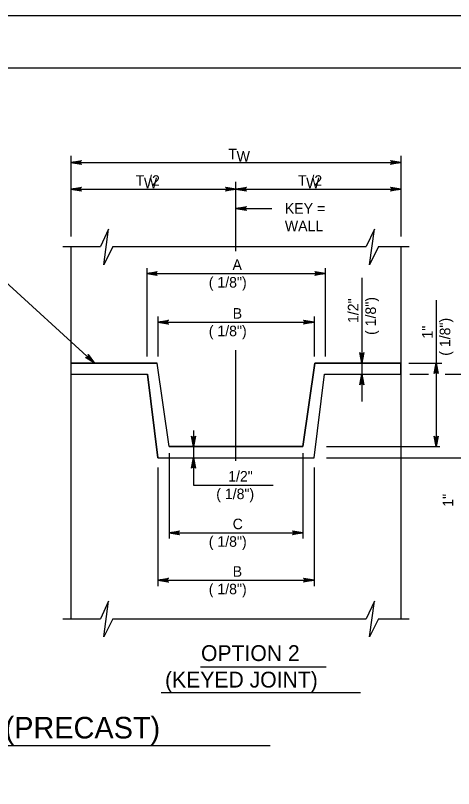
# Model space of a CAD drawing. Extents: x 2106427 to 2114911, y 988717 to 990787.
# Drawn here: x 2113594 to 2114003, y 990066 to 990787 of the extents above; entities that cross this region are included whole.
import ezdxf

# ---------------------------------------------------------------- set-up
doc = ezdxf.new("R2010")
doc.units = 0
for name, color, linetype in [('1', 7, 'Continuous'), ('3', 7, 'Continuous'), ('PLT-BNDY', 7, 'Continuous')]:
    doc.layers.add(name, color=color, linetype=linetype)

msp = doc.modelspace()

# ---------------------------------------------------------------- linework, layer by layer
at = {"layer": '1'}
for p, q in [((2113668.04, 990462.73), (2113413.04, 990695.31)), ((2113645.92, 990656.31), (2113645.92, 990580.81)), ((2113954.08, 990656.31), (2113954.08, 990580.81)), ((2113645.92, 990650.07), (2113954.08, 990650.07)), ((2113800, 990567.15), (2113800, 990631.9)), ((2113645.92, 990625.07), (2113800, 990625.07)), ((2113800, 990625.07), (2113954.08, 990625.07)), ((2113800, 990607.15), (2113833.59, 990607.15)), ((2113638.39, 990571.62), (2113673.37, 990571.62)), ((2113645.92, 990571.62), (2113645.92, 990224.14)), ((2113684.91, 990571.62), (2113921.57, 990571.62)), ((2113933.12, 990571.62), (2113961.82, 990571.62)), ((2113954.08, 990571.62), (2113954.08, 990224.14)), ((2113716.7, 990551.45), (2113716.7, 990469)), ((2113883.3, 990551.45), (2113883.3, 990469)), ((2113716.7, 990546.39), (2113883.3, 990546.39)), ((2113917.6, 990542.37), (2113917.6, 990426.83)), ((2113986.98, 990521.47), (2113986.98, 990384.77)), ((2113727.1, 990506.28), (2113727.1, 990469)), ((2113872.9, 990506.28), (2113872.9, 990469)), ((2113727.1, 990500.97), (2113872.9, 990500.97)), ((2113800, 990371.42), (2113800, 990474.89)), ((2113645.92, 990462.73), (2113726.38, 990462.73)), ((2113737.5, 990384.77), (2113726.38, 990462.73)), ((2113862.5, 990384.77), (2113873.62, 990462.73)), ((2113873.62, 990462.73), (2113954.08, 990462.73)), ((2113961.41, 990462.73), (2113992.31, 990462.73)), ((2113645.92, 990452.33), (2113717.37, 990452.33)), ((2113727.1, 990374.37), (2113717.37, 990452.33)), ((2113872.9, 990374.37), (2113882.63, 990452.33)), ((2113882.63, 990452.33), (2113954.08, 990452.33)), ((2113962.49, 990452.33), (2113979.72, 990452.33)), ((2113995.36, 990452.33), (2114012.79, 990452.33)), ((2113760.38, 990399.89), (2113760.38, 990348.86)), ((2113737.5, 990384.77), (2113862.5, 990384.77)), ((2113884.51, 990384.77), (2113990.36, 990384.77)), ((2113737.5, 990378.55), (2113737.5, 990298.84)), ((2113862.5, 990378.55), (2113862.5, 990298.84)), ((2113727.1, 990374.37), (2113872.9, 990374.37)), ((2113884.51, 990374.37), (2114011.3, 990374.37)), ((2113727.1, 990365.41), (2113727.1, 990254.47)), ((2113872.9, 990365.41), (2113872.9, 990254.47)), ((2113760.38, 990348.86), (2113834.77, 990348.86)), ((2113737.5, 990304.37), (2113862.5, 990304.37)), ((2113727.1, 990260.02), (2113872.9, 990260.02)), ((2113638.39, 990224.14), (2113673.37, 990224.14)), ((2113684.91, 990224.14), (2113921.57, 990224.14)), ((2113933.12, 990224.14), (2113961.82, 990224.14)), ((2113766.99, 990179.08), (2113884.25, 990179.08)), ((2113730.28, 990155.32), (2113916.43, 990155.32)), ((2113375.97, 990105.8), (2113831.83, 990105.8))]:
    msp.add_line(p, q, dxfattribs=at)
for points in [[(2114651.58, 988887.71), (2114651.58, 990738.11), (2112072.84, 990738.11), (2112072.84, 988887.71), (2114651.58, 988887.71), (2114651.58, 988974.19), (2113995.41, 988974.19), (2113995.41, 989186.39), (2114651.58, 989186.39), (2114651.58, 989281.41), (2113995.41, 989281.41), (2113995.41, 988887.71), (2114253.94, 988887.71), (2114253.94, 988974.19), (2114253.94, 988887.71), (2114506.57, 988887.71), (2114506.57, 988974.19), (2114506.57, 988933.79), (2114651.58, 988933.79)], [(2113645.92, 990650.07), (2113655.71, 990651.91), (2113655.33, 990651.65), (2113654.95, 990651.39), (2113654.76, 990651.06), (2113654.57, 990650.73), (2113654.51, 990650.4), (2113654.45, 990650.07), (2113654.51, 990649.75), (2113654.57, 990649.42), (2113654.76, 990649.09), (2113654.95, 990648.76), (2113655.33, 990648.5), (2113655.71, 990648.24), (2113645.92, 990650.07), (2113655.33, 990648.5), (2113654.95, 990648.76), (2113645.92, 990650.07), (2113654.76, 990649.09), (2113654.57, 990649.42), (2113645.92, 990650.07), (2113654.51, 990649.75), (2113654.45, 990650.07), (2113645.92, 990650.07), (2113654.51, 990650.4), (2113654.57, 990650.73), (2113645.92, 990650.07), (2113654.76, 990651.06), (2113654.95, 990651.39), (2113645.92, 990650.07), (2113655.33, 990651.65)], [(2113954.08, 990650.07), (2113944.29, 990648.24), (2113944.67, 990648.5), (2113945.05, 990648.76), (2113945.24, 990649.09), (2113945.44, 990649.42), (2113945.49, 990649.75), (2113945.55, 990650.07), (2113945.49, 990650.4), (2113945.44, 990650.73), (2113945.24, 990651.06), (2113945.05, 990651.39), (2113944.67, 990651.65), (2113944.29, 990651.91), (2113954.08, 990650.07), (2113944.67, 990651.65), (2113945.05, 990651.39), (2113954.08, 990650.07), (2113945.24, 990651.06), (2113945.44, 990650.73), (2113954.08, 990650.07), (2113945.49, 990650.4), (2113945.55, 990650.07), (2113954.08, 990650.07), (2113945.49, 990649.75), (2113945.44, 990649.42), (2113954.08, 990650.07), (2113945.24, 990649.09), (2113945.05, 990648.76), (2113954.08, 990650.07), (2113944.67, 990648.5)], [(2113645.92, 990625.07), (2113655.71, 990626.91), (2113655.33, 990626.65), (2113654.95, 990626.39), (2113654.76, 990626.06), (2113654.57, 990625.73), (2113654.51, 990625.4), (2113654.45, 990625.07), (2113654.51, 990624.75), (2113654.57, 990624.42), (2113654.76, 990624.09), (2113654.95, 990623.76), (2113655.33, 990623.5), (2113655.71, 990623.24), (2113645.92, 990625.07), (2113655.33, 990623.5), (2113654.95, 990623.76), (2113645.92, 990625.07), (2113654.76, 990624.09), (2113654.57, 990624.42), (2113645.92, 990625.07), (2113654.51, 990624.75), (2113654.45, 990625.07), (2113645.92, 990625.07), (2113654.51, 990625.4), (2113654.57, 990625.73), (2113645.92, 990625.07), (2113654.76, 990626.06), (2113654.95, 990626.39), (2113645.92, 990625.07), (2113655.33, 990626.65)], [(2113800, 990625.07), (2113790.22, 990623.24), (2113790.59, 990623.5), (2113790.97, 990623.76), (2113791.16, 990624.09), (2113791.36, 990624.42), (2113791.41, 990624.75), (2113791.47, 990625.07), (2113791.41, 990625.4), (2113791.36, 990625.73), (2113791.16, 990626.06), (2113790.97, 990626.39), (2113790.59, 990626.65), (2113790.22, 990626.91), (2113800, 990625.07), (2113790.59, 990626.65), (2113790.97, 990626.39), (2113800, 990625.07), (2113791.16, 990626.06), (2113791.36, 990625.73), (2113800, 990625.07), (2113791.41, 990625.4), (2113791.47, 990625.07), (2113800, 990625.07), (2113791.41, 990624.75), (2113791.36, 990624.42), (2113800, 990625.07), (2113791.16, 990624.09), (2113790.97, 990623.76), (2113800, 990625.07), (2113790.59, 990623.5)], [(2113800, 990625.07), (2113809.79, 990626.91), (2113809.41, 990626.65), (2113809.03, 990626.39), (2113808.84, 990626.06), (2113808.64, 990625.73), (2113808.59, 990625.4), (2113808.53, 990625.07), (2113808.59, 990624.75), (2113808.64, 990624.42), (2113808.84, 990624.09), (2113809.03, 990623.76), (2113809.41, 990623.5), (2113809.79, 990623.24), (2113800, 990625.07), (2113809.41, 990623.5), (2113809.03, 990623.76), (2113800, 990625.07), (2113808.84, 990624.09), (2113808.64, 990624.42), (2113800, 990625.07), (2113808.59, 990624.75), (2113808.53, 990625.07), (2113800, 990625.07), (2113808.59, 990625.4), (2113808.64, 990625.73), (2113800, 990625.07), (2113808.84, 990626.06), (2113809.03, 990626.39), (2113800, 990625.07), (2113809.41, 990626.65)], [(2113954.08, 990625.07), (2113944.29, 990623.24), (2113944.67, 990623.5), (2113945.05, 990623.76), (2113945.24, 990624.09), (2113945.44, 990624.42), (2113945.49, 990624.75), (2113945.55, 990625.07), (2113945.49, 990625.4), (2113945.44, 990625.73), (2113945.24, 990626.06), (2113945.05, 990626.39), (2113944.67, 990626.65), (2113944.29, 990626.91), (2113954.08, 990625.07), (2113944.67, 990626.65), (2113945.05, 990626.39), (2113954.08, 990625.07), (2113945.24, 990626.06), (2113945.44, 990625.73), (2113954.08, 990625.07), (2113945.49, 990625.4), (2113945.55, 990625.07), (2113954.08, 990625.07), (2113945.49, 990624.75), (2113945.44, 990624.42), (2113954.08, 990625.07), (2113945.24, 990624.09), (2113945.05, 990623.76), (2113954.08, 990625.07), (2113944.67, 990623.5)], [(2113800, 990607.15), (2113809.79, 990608.98), (2113809.41, 990608.72), (2113809.03, 990608.46), (2113808.84, 990608.13), (2113808.64, 990607.8), (2113808.59, 990607.48), (2113808.53, 990607.15), (2113808.59, 990606.82), (2113808.64, 990606.49), (2113808.84, 990606.16), (2113809.03, 990605.84), (2113809.41, 990605.57), (2113809.79, 990605.31), (2113800, 990607.15), (2113809.41, 990605.57), (2113809.03, 990605.84), (2113800, 990607.15), (2113808.84, 990606.16), (2113808.64, 990606.49), (2113800, 990607.15), (2113808.59, 990606.82), (2113808.53, 990607.15), (2113800, 990607.15), (2113808.59, 990607.48), (2113808.64, 990607.8), (2113800, 990607.15), (2113808.84, 990608.13), (2113809.03, 990608.46), (2113800, 990607.15), (2113809.41, 990608.72)], [(2113684.91, 990571.62), (2113676.59, 990554.6), (2113681.12, 990587.9), (2113673.37, 990571.62)], [(2113933.12, 990571.62), (2113924.79, 990554.6), (2113929.32, 990587.9), (2113921.57, 990571.62)], [(2113716.7, 990546.39), (2113726.49, 990548.23), (2113726.11, 990547.96), (2113725.73, 990547.7), (2113725.54, 990547.38), (2113725.34, 990547.05), (2113725.29, 990546.72), (2113725.23, 990546.39), (2113725.29, 990546.06), (2113725.34, 990545.74), (2113725.54, 990545.41), (2113725.73, 990545.08), (2113726.11, 990544.82), (2113726.49, 990544.56), (2113716.7, 990546.39), (2113726.11, 990544.82), (2113725.73, 990545.08), (2113716.7, 990546.39), (2113725.54, 990545.41), (2113725.34, 990545.74), (2113716.7, 990546.39), (2113725.29, 990546.06), (2113725.23, 990546.39), (2113716.7, 990546.39), (2113725.29, 990546.72), (2113725.34, 990547.05), (2113716.7, 990546.39), (2113725.54, 990547.38), (2113725.73, 990547.7), (2113716.7, 990546.39), (2113726.11, 990547.96)], [(2113883.3, 990546.39), (2113873.52, 990544.56), (2113873.89, 990544.82), (2113874.27, 990545.08), (2113874.46, 990545.41), (2113874.66, 990545.74), (2113874.71, 990546.06), (2113874.77, 990546.39), (2113874.71, 990546.72), (2113874.66, 990547.05), (2113874.46, 990547.38), (2113874.27, 990547.7), (2113873.89, 990547.96), (2113873.52, 990548.23), (2113883.3, 990546.39), (2113873.89, 990547.96), (2113874.27, 990547.7), (2113883.3, 990546.39), (2113874.46, 990547.38), (2113874.66, 990547.05), (2113883.3, 990546.39), (2113874.71, 990546.72), (2113874.77, 990546.39), (2113883.3, 990546.39), (2113874.71, 990546.06), (2113874.66, 990545.74), (2113883.3, 990546.39), (2113874.46, 990545.41), (2113874.27, 990545.08), (2113883.3, 990546.39), (2113873.89, 990544.82)], [(2113727.1, 990500.97), (2113736.89, 990502.81), (2113736.51, 990502.55), (2113736.13, 990502.28), (2113735.94, 990501.96), (2113735.74, 990501.63), (2113735.69, 990501.3), (2113735.63, 990500.97), (2113735.69, 990500.64), (2113735.74, 990500.32), (2113735.94, 990499.99), (2113736.13, 990499.66), (2113736.51, 990499.4), (2113736.89, 990499.14), (2113727.1, 990500.97), (2113736.51, 990499.4), (2113736.13, 990499.66), (2113727.1, 990500.97), (2113735.94, 990499.99), (2113735.74, 990500.32), (2113727.1, 990500.97), (2113735.69, 990500.64), (2113735.63, 990500.97), (2113727.1, 990500.97), (2113735.69, 990501.3), (2113735.74, 990501.63), (2113727.1, 990500.97), (2113735.94, 990501.96), (2113736.13, 990502.28), (2113727.1, 990500.97), (2113736.51, 990502.55)], [(2113872.9, 990500.97), (2113863.12, 990499.14), (2113863.49, 990499.4), (2113863.87, 990499.66), (2113864.06, 990499.99), (2113864.26, 990500.32), (2113864.31, 990500.64), (2113864.37, 990500.97), (2113864.31, 990501.3), (2113864.26, 990501.63), (2113864.06, 990501.96), (2113863.87, 990502.28), (2113863.49, 990502.55), (2113863.12, 990502.81), (2113872.9, 990500.97), (2113863.49, 990502.55), (2113863.87, 990502.28), (2113872.9, 990500.97), (2113864.06, 990501.96), (2113864.26, 990501.63), (2113872.9, 990500.97), (2113864.31, 990501.3), (2113864.37, 990500.97), (2113872.9, 990500.97), (2113864.31, 990500.64), (2113864.26, 990500.32), (2113872.9, 990500.97), (2113864.06, 990499.99), (2113863.87, 990499.66), (2113872.9, 990500.97), (2113863.49, 990499.4)], [(2113668.04, 990462.73), (2113659.57, 990467.97), (2113660.48, 990467.85), (2113661.21, 990468.07), (2113661.74, 990468.48), (2113662.09, 990469.04), (2113662.25, 990469.79), (2113662.04, 990470.68), (2113668.04, 990462.73), (2113662.25, 990469.79), (2113662.09, 990469.04), (2113668.04, 990462.73), (2113661.74, 990468.48), (2113661.21, 990468.07), (2113668.04, 990462.73), (2113660.48, 990467.85)], [(2113917.6, 990462.73), (2113915.76, 990472.52), (2113916.02, 990472.14), (2113916.28, 990471.76), (2113916.61, 990471.57), (2113916.94, 990471.38), (2113917.27, 990471.32), (2113917.6, 990471.26), (2113917.92, 990471.32), (2113918.25, 990471.38), (2113918.58, 990471.57), (2113918.91, 990471.76), (2113919.17, 990472.14), (2113919.43, 990472.52), (2113917.6, 990462.73), (2113919.17, 990472.14), (2113918.91, 990471.76), (2113917.6, 990462.73), (2113918.58, 990471.57), (2113918.25, 990471.38), (2113917.6, 990462.73), (2113917.92, 990471.32), (2113917.6, 990471.26), (2113917.6, 990462.73), (2113917.27, 990471.32), (2113916.94, 990471.38), (2113917.6, 990462.73), (2113916.61, 990471.57), (2113916.28, 990471.76), (2113917.6, 990462.73), (2113916.02, 990472.14)], [(2113986.98, 990462.73), (2113988.81, 990452.95), (2113988.55, 990453.32), (2113988.29, 990453.7), (2113987.96, 990453.9), (2113987.64, 990454.09), (2113987.31, 990454.15), (2113986.98, 990454.2), (2113986.65, 990454.15), (2113986.32, 990454.09), (2113985.99, 990453.9), (2113985.67, 990453.7), (2113985.41, 990453.32), (2113985.14, 990452.95), (2113986.98, 990462.73), (2113985.41, 990453.32), (2113985.67, 990453.7), (2113986.98, 990462.73), (2113985.99, 990453.9), (2113986.32, 990454.09), (2113986.98, 990462.73), (2113986.65, 990454.15), (2113986.98, 990454.2), (2113986.98, 990462.73), (2113987.31, 990454.15), (2113987.64, 990454.09), (2113986.98, 990462.73), (2113987.96, 990453.9), (2113988.29, 990453.7), (2113986.98, 990462.73), (2113988.55, 990453.32)], [(2113917.6, 990452.33), (2113919.43, 990442.55), (2113919.17, 990442.92), (2113918.91, 990443.3), (2113918.58, 990443.5), (2113918.25, 990443.69), (2113917.92, 990443.75), (2113917.6, 990443.8), (2113917.27, 990443.75), (2113916.94, 990443.69), (2113916.61, 990443.5), (2113916.28, 990443.3), (2113916.02, 990442.92), (2113915.76, 990442.55), (2113917.6, 990452.33), (2113916.02, 990442.92), (2113916.28, 990443.3), (2113917.6, 990452.33), (2113916.61, 990443.5), (2113916.94, 990443.69), (2113917.6, 990452.33), (2113917.27, 990443.75), (2113917.6, 990443.8), (2113917.6, 990452.33), (2113917.92, 990443.75), (2113918.25, 990443.69), (2113917.6, 990452.33), (2113918.58, 990443.5), (2113918.91, 990443.3), (2113917.6, 990452.33), (2113919.17, 990442.92)], [(2113760.38, 990384.77), (2113758.55, 990394.55), (2113758.81, 990394.17), (2113759.07, 990393.8), (2113759.4, 990393.6), (2113759.73, 990393.41), (2113760.06, 990393.35), (2113760.38, 990393.3), (2113760.71, 990393.35), (2113761.04, 990393.41), (2113761.37, 990393.6), (2113761.7, 990393.8), (2113761.96, 990394.17), (2113762.22, 990394.55), (2113760.38, 990384.77), (2113761.96, 990394.17), (2113761.7, 990393.8), (2113760.38, 990384.77), (2113761.37, 990393.6), (2113761.04, 990393.41), (2113760.38, 990384.77), (2113760.71, 990393.35), (2113760.38, 990393.3), (2113760.38, 990384.77), (2113760.06, 990393.35), (2113759.73, 990393.41), (2113760.38, 990384.77), (2113759.4, 990393.6), (2113759.07, 990393.8), (2113760.38, 990384.77), (2113758.81, 990394.17)], [(2113986.98, 990384.77), (2113985.14, 990394.55), (2113985.41, 990394.17), (2113985.67, 990393.8), (2113985.99, 990393.6), (2113986.32, 990393.41), (2113986.65, 990393.35), (2113986.98, 990393.3), (2113987.31, 990393.35), (2113987.64, 990393.41), (2113987.96, 990393.6), (2113988.29, 990393.8), (2113988.55, 990394.17), (2113988.81, 990394.55), (2113986.98, 990384.77), (2113988.55, 990394.17), (2113988.29, 990393.8), (2113986.98, 990384.77), (2113987.96, 990393.6), (2113987.64, 990393.41), (2113986.98, 990384.77), (2113987.31, 990393.35), (2113986.98, 990393.3), (2113986.98, 990384.77), (2113986.65, 990393.35), (2113986.32, 990393.41), (2113986.98, 990384.77), (2113985.99, 990393.6), (2113985.67, 990393.8), (2113986.98, 990384.77), (2113985.41, 990394.17)], [(2113760.38, 990374.37), (2113762.22, 990364.58), (2113761.96, 990364.96), (2113761.7, 990365.33), (2113761.37, 990365.53), (2113761.04, 990365.72), (2113760.71, 990365.78), (2113760.38, 990365.84), (2113760.06, 990365.78), (2113759.73, 990365.72), (2113759.4, 990365.53), (2113759.07, 990365.33), (2113758.81, 990364.96), (2113758.55, 990364.58), (2113760.38, 990374.37), (2113758.81, 990364.96), (2113759.07, 990365.33), (2113760.38, 990374.37), (2113759.4, 990365.53), (2113759.73, 990365.72), (2113760.38, 990374.37), (2113760.06, 990365.78), (2113760.38, 990365.84), (2113760.38, 990374.37), (2113760.71, 990365.78), (2113761.04, 990365.72), (2113760.38, 990374.37), (2113761.37, 990365.53), (2113761.7, 990365.33), (2113760.38, 990374.37), (2113761.96, 990364.96)], [(2113737.5, 990304.37), (2113747.29, 990306.21), (2113746.91, 990305.94), (2113746.53, 990305.68), (2113746.34, 990305.36), (2113746.14, 990305.03), (2113746.09, 990304.7), (2113746.03, 990304.37), (2113746.09, 990304.04), (2113746.14, 990303.71), (2113746.34, 990303.39), (2113746.53, 990303.06), (2113746.91, 990302.8), (2113747.29, 990302.54), (2113737.5, 990304.37), (2113746.91, 990302.8), (2113746.53, 990303.06), (2113737.5, 990304.37), (2113746.34, 990303.39), (2113746.14, 990303.71), (2113737.5, 990304.37), (2113746.09, 990304.04), (2113746.03, 990304.37), (2113737.5, 990304.37), (2113746.09, 990304.7), (2113746.14, 990305.03), (2113737.5, 990304.37), (2113746.34, 990305.36), (2113746.53, 990305.68), (2113737.5, 990304.37), (2113746.91, 990305.94)], [(2113862.5, 990304.37), (2113852.72, 990302.54), (2113853.09, 990302.8), (2113853.47, 990303.06), (2113853.66, 990303.39), (2113853.86, 990303.71), (2113853.91, 990304.04), (2113853.97, 990304.37), (2113853.91, 990304.7), (2113853.86, 990305.03), (2113853.66, 990305.36), (2113853.47, 990305.68), (2113853.09, 990305.94), (2113852.72, 990306.21), (2113862.5, 990304.37), (2113853.09, 990305.94), (2113853.47, 990305.68), (2113862.5, 990304.37), (2113853.66, 990305.36), (2113853.86, 990305.03), (2113862.5, 990304.37), (2113853.91, 990304.7), (2113853.97, 990304.37), (2113862.5, 990304.37), (2113853.91, 990304.04), (2113853.86, 990303.71), (2113862.5, 990304.37), (2113853.66, 990303.39), (2113853.47, 990303.06), (2113862.5, 990304.37), (2113853.09, 990302.8)], [(2113727.1, 990260.02), (2113736.89, 990261.86), (2113736.51, 990261.6), (2113736.13, 990261.34), (2113735.94, 990261.01), (2113735.74, 990260.68), (2113735.69, 990260.35), (2113735.63, 990260.02), (2113735.69, 990259.7), (2113735.74, 990259.37), (2113735.94, 990259.04), (2113736.13, 990258.71), (2113736.51, 990258.45), (2113736.89, 990258.19), (2113727.1, 990260.02), (2113736.51, 990258.45), (2113736.13, 990258.71), (2113727.1, 990260.02), (2113735.94, 990259.04), (2113735.74, 990259.37), (2113727.1, 990260.02), (2113735.69, 990259.7), (2113735.63, 990260.02), (2113727.1, 990260.02), (2113735.69, 990260.35), (2113735.74, 990260.68), (2113727.1, 990260.02), (2113735.94, 990261.01), (2113736.13, 990261.34), (2113727.1, 990260.02), (2113736.51, 990261.6)], [(2113872.9, 990260.02), (2113863.12, 990258.19), (2113863.49, 990258.45), (2113863.87, 990258.71), (2113864.06, 990259.04), (2113864.26, 990259.37), (2113864.31, 990259.7), (2113864.37, 990260.02), (2113864.31, 990260.35), (2113864.26, 990260.68), (2113864.06, 990261.01), (2113863.87, 990261.34), (2113863.49, 990261.6), (2113863.12, 990261.86), (2113872.9, 990260.02), (2113863.49, 990261.6), (2113863.87, 990261.34), (2113872.9, 990260.02), (2113864.06, 990261.01), (2113864.26, 990260.68), (2113872.9, 990260.02), (2113864.31, 990260.35), (2113864.37, 990260.02), (2113872.9, 990260.02), (2113864.31, 990259.7), (2113864.26, 990259.37), (2113872.9, 990260.02), (2113864.06, 990259.04), (2113863.87, 990258.71), (2113872.9, 990260.02), (2113863.49, 990258.45)], [(2113684.91, 990224.14), (2113676.59, 990207.13), (2113681.12, 990240.43), (2113673.37, 990224.14)], [(2113933.12, 990224.14), (2113924.79, 990207.13), (2113929.32, 990240.43), (2113921.57, 990224.14)]]:
    msp.add_lwpolyline(points, dxfattribs=at)
msp.add_lwpolyline([(2113645.92, 990462.73), (2113645.92, 990452.33), (2113717.37, 990452.33), (2113727.1, 990374.37), (2113872.9, 990374.37), (2113882.63, 990452.33), (2113954.08, 990452.33), (2113954.08, 990462.73), (2113873.62, 990462.73), (2113862.5, 990384.77), (2113737.5, 990384.77), (2113726.38, 990462.73)], close=True, dxfattribs=at)
at = {"layer": 'PLT-BNDY'}
msp.add_lwpolyline([(2111944.88, 990787.32), (2114704.07, 990787.32), (2114704.07, 988838.5), (2111944.88, 988838.5)], close=True, dxfattribs=at)

# ---------------------------------------------------------------- texts
at = {"layer": '3'}
for s, height, p in [('T ', 9.843, (2113792.86, 990653.04)), ('W', 9.84, (2113800.63, 990650.82)), ('T /2', 9.843, (2113706.26, 990628.26)), ('W', 9.84, (2113714.03, 990626.04)), ('T /2', 9.843, (2113857.82, 990628.26)), ('W', 9.84, (2113865.59, 990626.04)), ('  KEY =', 9.843, (2113838.33, 990602.26)), ('  WALL', 9.843, (2113838.33, 990585.86)), ('A', 9.84, (2113796.78, 990549.67)), ('( 1/8")', 9.843, (2113774.62, 990533.27)), ('B', 9.84, (2113796.94, 990504.25)), ('( 1/8")', 9.843, (2113774.62, 990487.85)), ('1/2"', 9.843, (2113792.72, 990352.14)), ('( 1/8")', 9.843, (2113781.6, 990335.74)), ('C', 9.84, (2113796.94, 990307.65)), ('( 1/8")', 9.843, (2113774.62, 990291.25)), ('B', 9.84, (2113796.94, 990263.3)), ('( 1/8")', 9.843, (2113774.62, 990246.9)), ('OPTION 2', 14.764, (2113767.38, 990184.61)), ('(KEYED JOINT)', 14.7638, (2113733.78, 990159.85)), ('JOINT DETAILS (PRECAST)', 20.1575, (2113378.77, 990112.29))]:
    msp.add_text(s, height=height, dxfattribs=at).set_placement(p)
for s, p in [('1/2"', (2113914.32, 990500.16)), ('( 1/8")', (2113930.72, 990489.04)), ('( 1/8")', (2114000.1, 990469.59)), ('1"', (2113983.7, 990485.63)), ('1"', (2114002.89, 990328.66))]:
    msp.add_text(s, height=9.843, rotation=90, dxfattribs=at).set_placement(p)

doc.saveas('drawing.dxf')
